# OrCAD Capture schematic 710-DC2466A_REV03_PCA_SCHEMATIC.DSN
size B; note: WIDE VIN RANGE BUCK-BOOST CHARGE PUMP WITH WATCHDOG TIMER
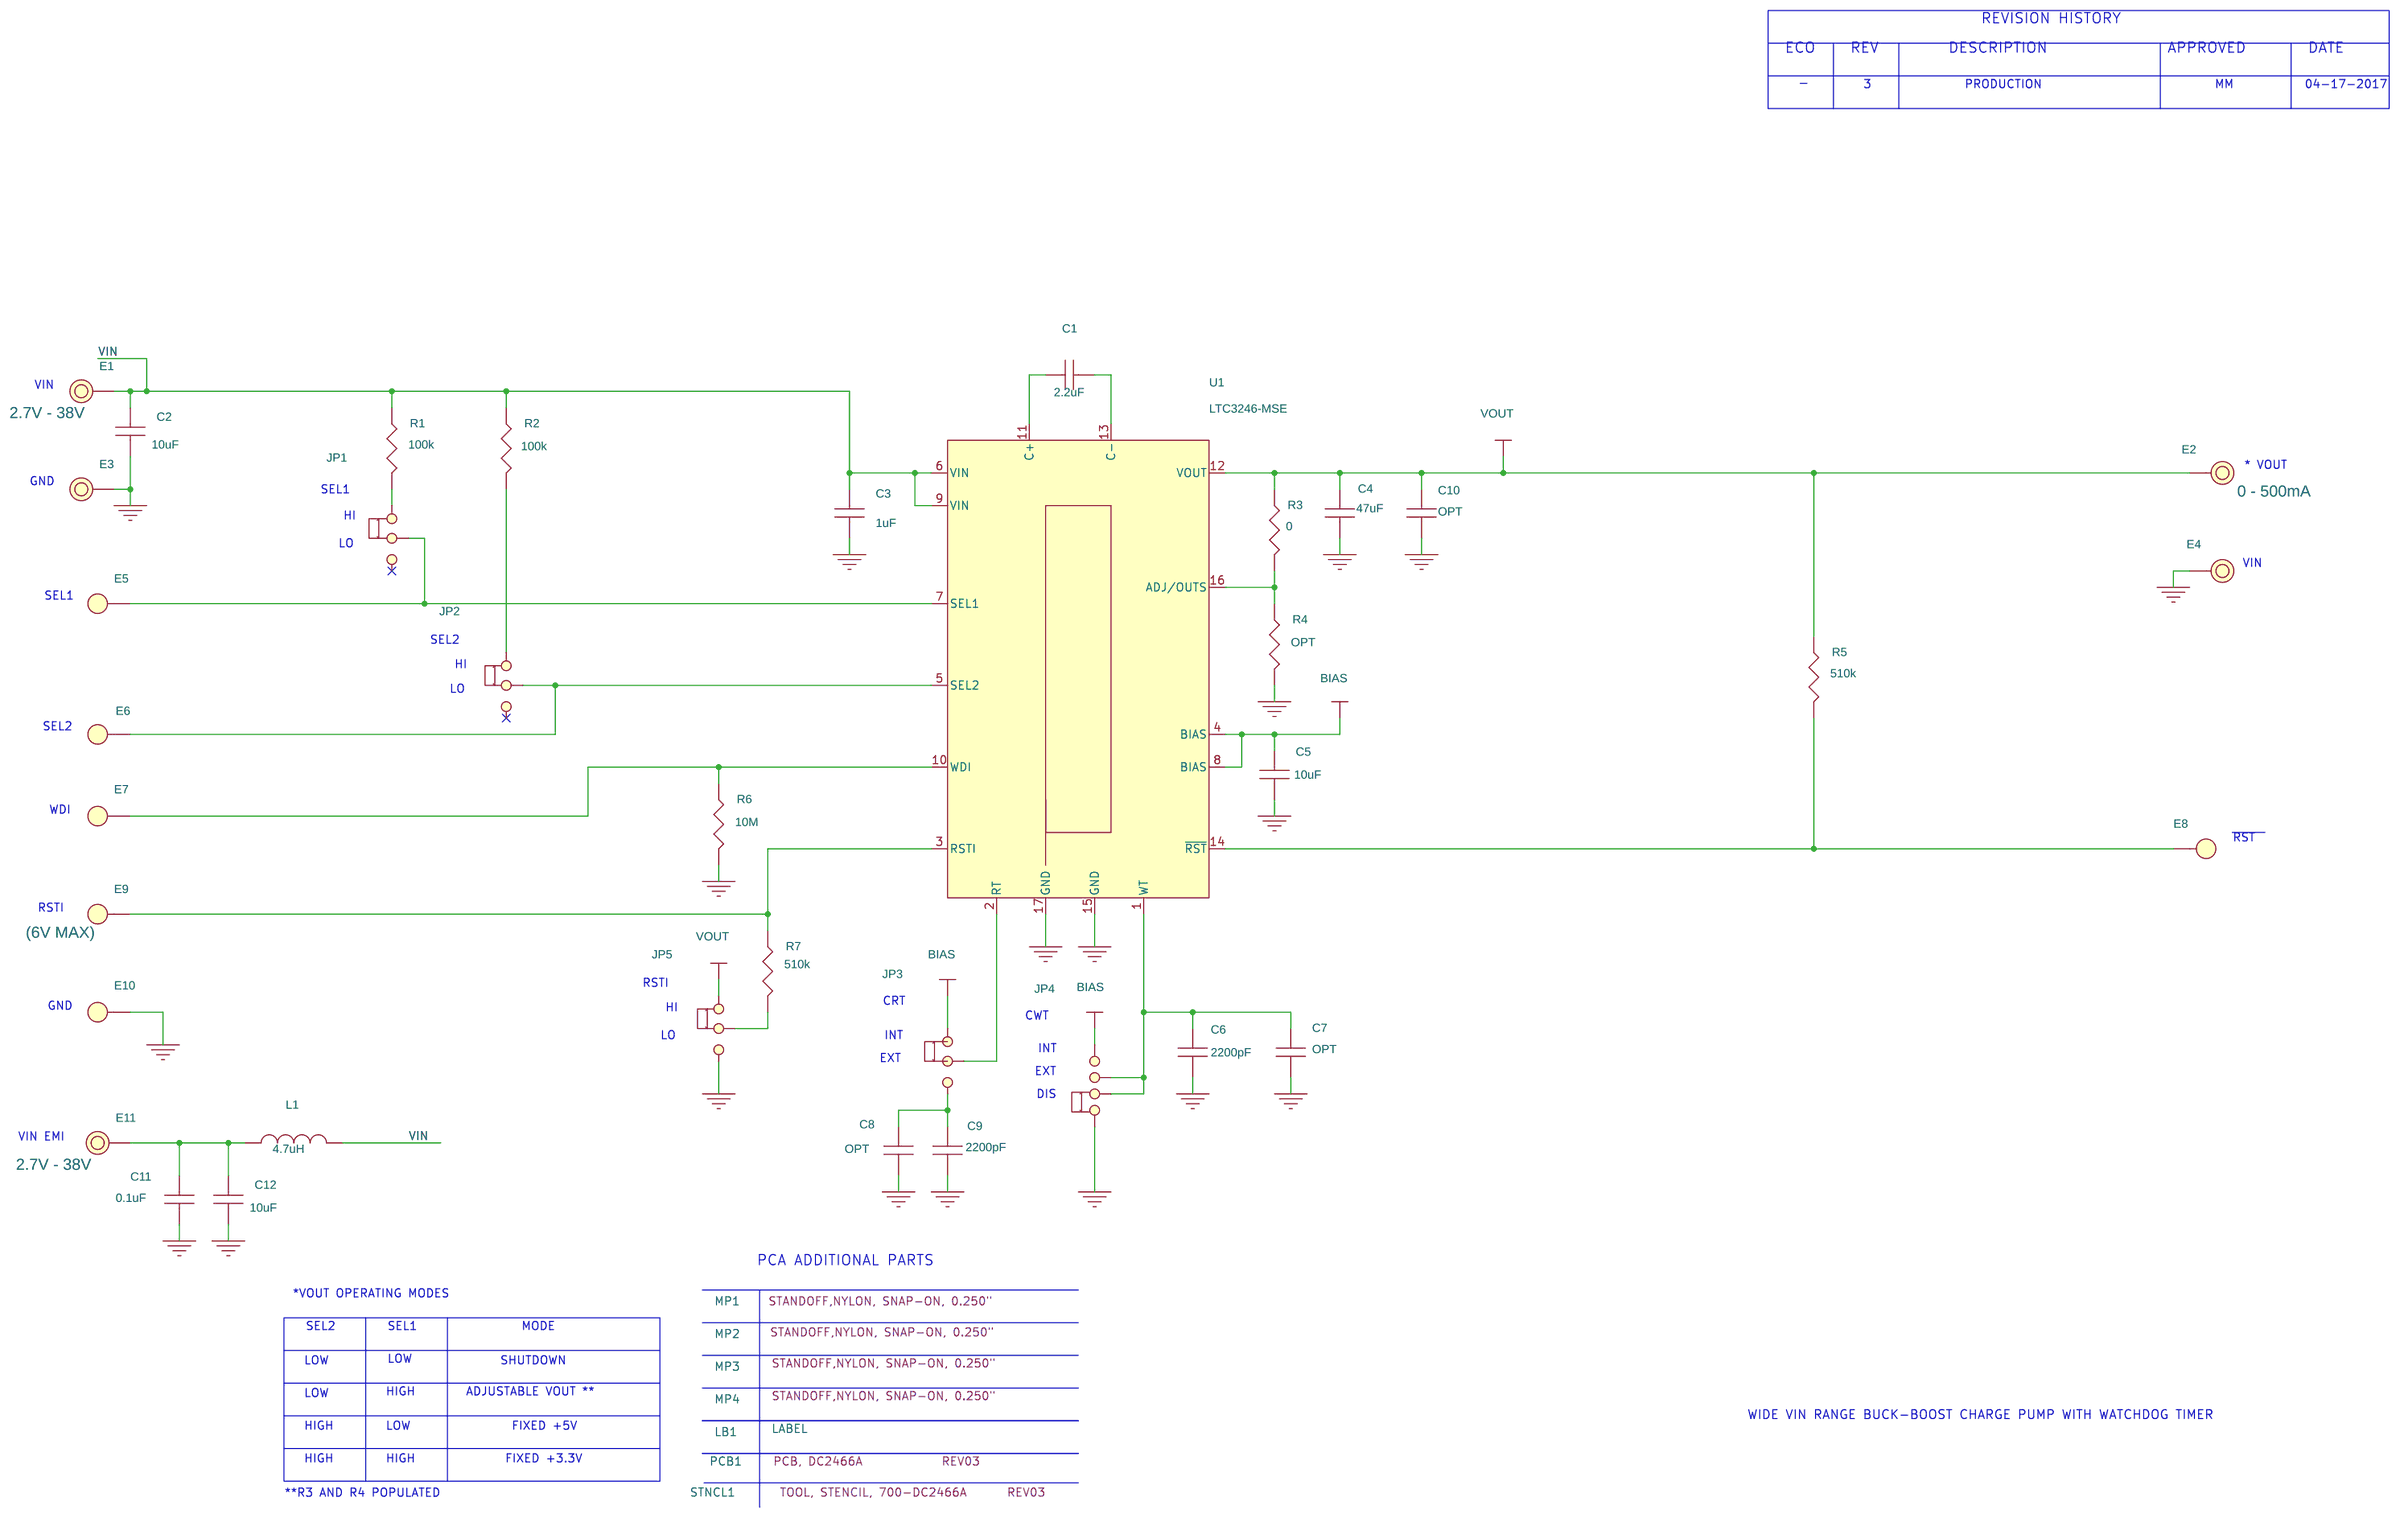
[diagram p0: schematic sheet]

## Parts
C1  2.2uF  [CC0603N]
C2  10uF  [CC1206N]
C3  1uF  [CC0805N]
C4  47uF  [CC0603N]
C5  10uF  [CC0603M]
C6  2200pF  [CC0402N]
C7  OPT  [CC0402N]
C8  OPT  [CC0402N]
C9  2200pF  [CC0402N]
C10  OPT  [CC0805N]
C11  0.1uF  [CC0402N]
C12  10uF  [CC1206N]
E1  TEST POINT  [MILLMAX2501]
E2  TEST POINT  [MILLMAX2501]
E3  TEST POINT  [MILLMAX2501]
E4  TEST POINT  [MILLMAX2501]
E5  TEST POINT  [MILLMAX2308]
E6  TEST POINT  [MILLMAX2308]
E7  TEST POINT  [MILLMAX2308]
E8  TEST POINT  [MILLMAX2308]
E9  TEST POINT  [MILLMAX2308]
E10  TEST POINT  [MILLMAX2308]
E11  TEST POINT  [MILLMAX2501]
JP1  HDR  [HD1X3-079]
JP2  HDR  [HD1X3-079]
JP3  HDR  [HD1X3-079]
JP4  HDR  [JP4X1/079]
JP5  HDR  [HD1X3-079]
L1  4.7uH  [TDK_VLF302515]
LB1  LABEL  [895-0154_REV01]
MP1  STANDOFF  [MTG-8831]
MP2  STANDOFF  [MTG-8831]
MP3  STANDOFF  [MTG-8831]
MP4  STANDOFF  [MTG-8831]
PCB1  PCB, DC2466A
R1  100k  [CR0402N]
R2  100k  [CR0402N]
R3  0  [CR0402N]
R4  OPT  [CR0402N]
R5  510k  [CR0402N]
R6  10M  [CR0402N]
R7  510k  [CR0402N]
STNCL1  TOOL, STENCIL, 700-DC2466A
U1  LTC3246-MSE  [LTC-MSE-16-1667]
XJP1  SHUNT
XJP2  SHUNT
XJP3  SHUNT
XJP4  SHUNT
XJP5  SHUNT

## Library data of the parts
C1 = CAP: CAP.,2.2uF,X5R,10V,10%,0603,NO SUBS. ALLOWED; CLASS: DISCRETE; Dielectric Type: X5R; Manufacturer: MURATA; Manufacturer PN: GRM188R61A225KE34D; PART_NUMBER: 150-0168; Package Size: 0603; Package Type: SMD; Rated Voltage: 10V; Tolerance: 10%; UserField01: NO SUBS. ALLOWED
C2 C12 = CAP: CAP.,10uF,X5R,50V,10%,1206,NO SUBS. ALLOWED; CLASS: DISCRETE; Dielectric Type: X5R; Manufacturer: TDK; Manufacturer PN: C3216X5R1H106K160AB; PART_NUMBER: 150-2430; Package Size: 1206; Package Type: SMD; Rated Voltage: 50V; Tolerance: 10%; UserField01: NO SUBS. ALLOWED
C3 = CAP: CAP.,1uF,X7R,50V,10%,0805, NO SUBS. ALLOWED; CLASS: DISCRETE; Dielectric Type: X7R; Manufacturer: TAIYO YUDEN; Manufacturer PN: UMK212B7105KG-T; PART_NUMBER: TMP-2555; Package Size: 0805; Rated Voltage: 50V; Tolerance: 10%
C4 = CAP: CAP.,47uF,X5R,6.3V,20%,0603,NO SUBS. ALLOWED; CLASS: DISCRETE; Dielectric Type: X5R; Manufacturer: MURATA; Manufacturer PN: GRM188R60J476ME15D; PART_NUMBER: 150-2392; Package Size: 0603; Package Type: Surface Mount, MLCC; Rated Voltage: 6.3V; Temperature Coefficient: X5R; Tolerance: 20%; UserField01: NO SUBS. ALLOWED
C5 = CAP: CAP.,10uF,X5R,6.3V,10%,0603,NO SUBS. ALLOWED; CLASS: DISCRETE; Dielectric Type: X5R; FPLIST: CC0603L,CC0603N,CC0603M; Manufacturer: TDK; Manufacturer PN: C1608X5R0J106K080AB; PART_NUMBER: 150-2431; Package Size: 0603; Package Type: Surface Mount, MLCC; Rated Voltage: 6.3V; Temperature Coefficient: X5R; Tolerance: 10%; UserField01: NO SUBS. ALLOWED
C6 C9 = CAP: CAP.,2200pF,C0G,25V,5%,0402,NO SUBS. ALLOWED; CLASS: DISCRETE; Dielectric Type: C0G; Manufacturer: KEMET; Manufacturer PN: C0402C222J3GACTU; PART_NUMBER: 150-3239; Package Size: 0402; Package Type: SMD; Rated Voltage: 25V; Tolerance: 5%; UserField01: NO SUBS. ALLOWED
C7 C8 = CAP: CAP., OPTION, 0402; CLASS: DISCRETE; PART_NUMBER: 150-3148; Package Size: 0402; Package Type: SMD
C10 = CAP: CAP., OPTION, 0805; CLASS: DISCRETE; PART_NUMBER: 150-3036; Package Size: 0805; Package Type: SMD
C11 = CAP: CAP.,0.1uF,X7R,50V,10%,0402, NO SUBS. ALLOWED; CLASS: DISCRETE; Dielectric Type: X7R; FPLIST: CC0402N,CC0402L,CC0402M; Manufacturer: MURATA; Manufacturer PN: GRM155R71H104KE14D; PART_NUMBER: TMP-2554; Package Size: 0402; Package Type: SMD; Rated Voltage: 50V; Tolerance: 10%
E1 E11 = TESTPOINT_.219_MILL-MAX_2501: TEST POINT,TURRET,0.094",MTG. HOLE; CLASS: IO; Manufacturer: MILL-MAX; Manufacturer PN: 2501-2-00-80-00-00-07-0; PART_NUMBER: 260-0003; Range: 2.7V - 38V
E2 = TESTPOINT_.219_MILL-MAX_2501: TEST POINT,TURRET,0.094",MTG. HOLE; CLASS: IO; IOUT: 0 - 500mA; Manufacturer: MILL-MAX; Manufacturer PN: 2501-2-00-80-00-00-07-0; PART_NUMBER: 260-0003
E3 E4 = TESTPOINT_.219_MILL-MAX_2501: TEST POINT,TURRET,0.094",MTG. HOLE; CLASS: IO; Manufacturer: MILL-MAX; Manufacturer PN: 2501-2-00-80-00-00-07-0; PART_NUMBER: 260-0003
E5-E8 E10 = TEST_POINT_.156_MILL-MAX_2308: TEST POINT,TURRET,0.064",MTG. HOLE; CLASS: IO; Manufacturer PN: 2308-2-00-80-00-00-07-0; PART_NUMBER: 260-0004
E9 = TEST_POINT_.156_MILL-MAX_2308: TEST POINT,TURRET,0.064",MTG. HOLE; CLASS: IO; Manufacturer PN: 2308-2-00-80-00-00-07-0; PART_NUMBER: 260-0004; RANGE: (6V MAX)
JP1-JP3 JP5 = 3_PIN_HEADER_.079_SINGLE_ROW: CONN.,HDR,MALE,1x3,2mm,THT, STR; CLASS: IO; Manufacturer: Wurth Elektronik; Manufacturer PN: 62000311121; PART_NUMBER: 250-0484
JP4 = HD1X4-079: CONN.,HDR,MALE,1x4,2mm,THT, STR; CLASS: IO; Manufacturer: WURTH ELEKTRONIK; Manufacturer PN: 62000411121; PART_NUMBER: 250-0563
L1 = IND_ALT: IND.,4.7uH,FERRITE,20%,1.95A,90mOHMS,3mmx2.5mmx1.5mm; CLASS: DISCRETE; Manufacturer: TDK; Manufacturer PN: VLF302515MT-4R7M; PART_NUMBER: 200-0489; Package Size: 3mmx2.5mmx1.5mm; Tolerance: 20%
LB1 = BLANK_LABEL: LABEL SPEC, DEMO BOARD SERIAL NUMBER; Manufacturer: BRADY; Manufacturer PN: THT-96-717-10; PART_NUMBER: 895-0154
MP1-MP4 = BLANK_MECHANICAL_PART: STANDOFF,NYLON, SNAP-ON, 0.250"; CLASS: MECHANICAL PART; Manufacturer: KEYSTONE; Manufacturer PN: 8831; PART_NUMBER: 763-0006
PCB1 = BLANK_PCB_PART: BOM Notes: REV03; CLASS: PCB; Manufacturer: EAGLE ELECTRONICS INC.; Manufacturer PN: 600-DC2466A; PART_NUMBER: 600-DC2466A
R1 R2 = RES: RES.,100k OHMS,5%,1/16W,0402; CLASS: DISCRETE; Manufacturer: YAGEO; Manufacturer PN: RC0402JR-07100KL; PART_NUMBER: 100-0058; Package Size: 0402; Rated Power: 1/16W; Temperature Coefficient: 100ppm/C; Tolerance: 5%
R3 = RES: RES.,0 OHM,1/16W,0402; CLASS: DISCRETE; Manufacturer: ROHM; Manufacturer PN: MCR01MZPJ000; PART_NUMBER: 100-0025; Package Size: 0402; Rated Power: 1/16W
R4 = RES: RES., OPTION, 0402; CLASS: DISCRETE; PART_NUMBER: 100-0357; Package Size: 0402
R5 R7 = RES: RES.,510k OHMS,5%,1/16W,0402; CLASS: DISCRETE; Manufacturer: VISHAY; Manufacturer PN: CRCW0402510KJNED; PART_NUMBER: 100-2964; Package Size: 0402; Rated Power: 1/16W; Temperature Coefficient: 200ppm; Tolerance: 5%
R6 = RES: RES.,10M OHMS,5%,1/16W,0402; CLASS: DISCRETE; Manufacturer: VISHAY; Manufacturer PN: CRCW040210M0JNED; PART_NUMBER: 100-2965; Package Size: 0402; Rated Power: 1/16W; Temperature Coefficient: 200ppm; Tolerance: 5%
STNCL1 = BLANK_STENCIL_PART: BOM Notes: REV03; CLASS: DISCRETE; Manufacturer: LINEAR TECH.; Manufacturer PN: 830-DC2466; PART_NUMBER: 830-DC2466A
U1 = LTC3246-MSE: IC,Wide VIN Range BB Charge Pump,EMSE,with WD Timer; CLASS: IC; Manufacturer: LINEAR TECH.; Manufacturer PN: LTC3246EMSE#PBF; PART_NUMBER: LTC3246EMSE#PBF; Package Size: MSE16; Package Type: EMSE
XJP1-XJP5 = CONN_SHUNT_2_POS_2mm: CONN.,SHUNT,FEMALE,2 POS,2mm; CLASS: IO; Manufacturer: Wurth Elektronik; Manufacturer PN: 60800213421; PART_NUMBER: 250-0485

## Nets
GND: C2.2 C3.2 C4.2 C5.2 C6.2 C7.2 C8.2 C9.2 C10.2 C11.2 C12.2 E3.1 E4.1 E10.1(A) JP4.4 JP5.3 R4.2 R6.2 U1.15(GND) U1.17(GND)
VIN: C2.1 C3.1 E1.1 L1.2 R1.1 R2.1 U1.6(VIN) U1.9(VIN)
BIAS: C5.1 JP3.1 JP4.1 U1.4(BIAS) U1.8(BIAS)
VOUT: C4.1 C10.1 E2.1 JP5.1 R3.1 R5.1 U1.12(VOUT)
N16676763: E5.1(A) JP1.2 U1.7(SEL1)
N16676837: JP2.1 R2.2
N16676841: E6.1(A) JP2.2 U1.5(SEL2)
N16677148: E7.1(A) R6.1 U1.10(WDI)
N16677414: E9.1(A) R7.1 U1.3(RSTI)
N16677468: JP5.2 R7.2
N16677739: C1.1 U1.11(C+)
N16677748: C1.2 U1.13(C-)
N16679560: R3.2 R4.1 U1.16(ADJ/OUTS)
N16680383: C6.1 C7.1 JP4.2 JP4.3 U1.1(WT)
N16680452: JP3.2 U1.2(RT)
N16680461: C8.1 C9.1 JP3.3
N16681125: E8.1(A) R5.2 U1.14(~{RST})
N16701867: JP1.1 R1.2
N16722998: C11.1 C12.1 E11.1 L1.1

Not connected (* = marked no-connect by the designer): JP1 3*; JP2 3*

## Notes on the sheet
- REVISION HISTORY
- ECO
- REV
- DESCRIPTION
- APPROVED
- DATE
- -
- 3
- PRODUCTION
- MM
- 04-17-2017
- VIN
- * VOUT
- GND
- SEL1
- HI
- LO
- VIN
- SEL1
- SEL2
- HI
- LO
- SEL2
- WDI
- RST
- RSTI
- RSTI
- GND
- HI
- CRT
- CWT
- LO
- INT
- INT
- EXT
- EXT
- DIS
- VIN EMI
- PCA ADDITIONAL PARTS
- *VOUT OPERATING MODES
- SEL2
- SEL1
- MODE
- LOW
- LOW
- SHUTDOWN
- LOW
- HIGH
- ADJUSTABLE VOUT **
- WIDE VIN RANGE BUCK-BOOST CHARGE PUMP WITH WATCHDOG TIMER
- HIGH
- LOW
- FIXED +5V
- HIGH
- HIGH
- FIXED +3.3V
- **R3 AND R4 POPULATED
